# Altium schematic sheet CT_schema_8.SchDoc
size 254 x 194 mm
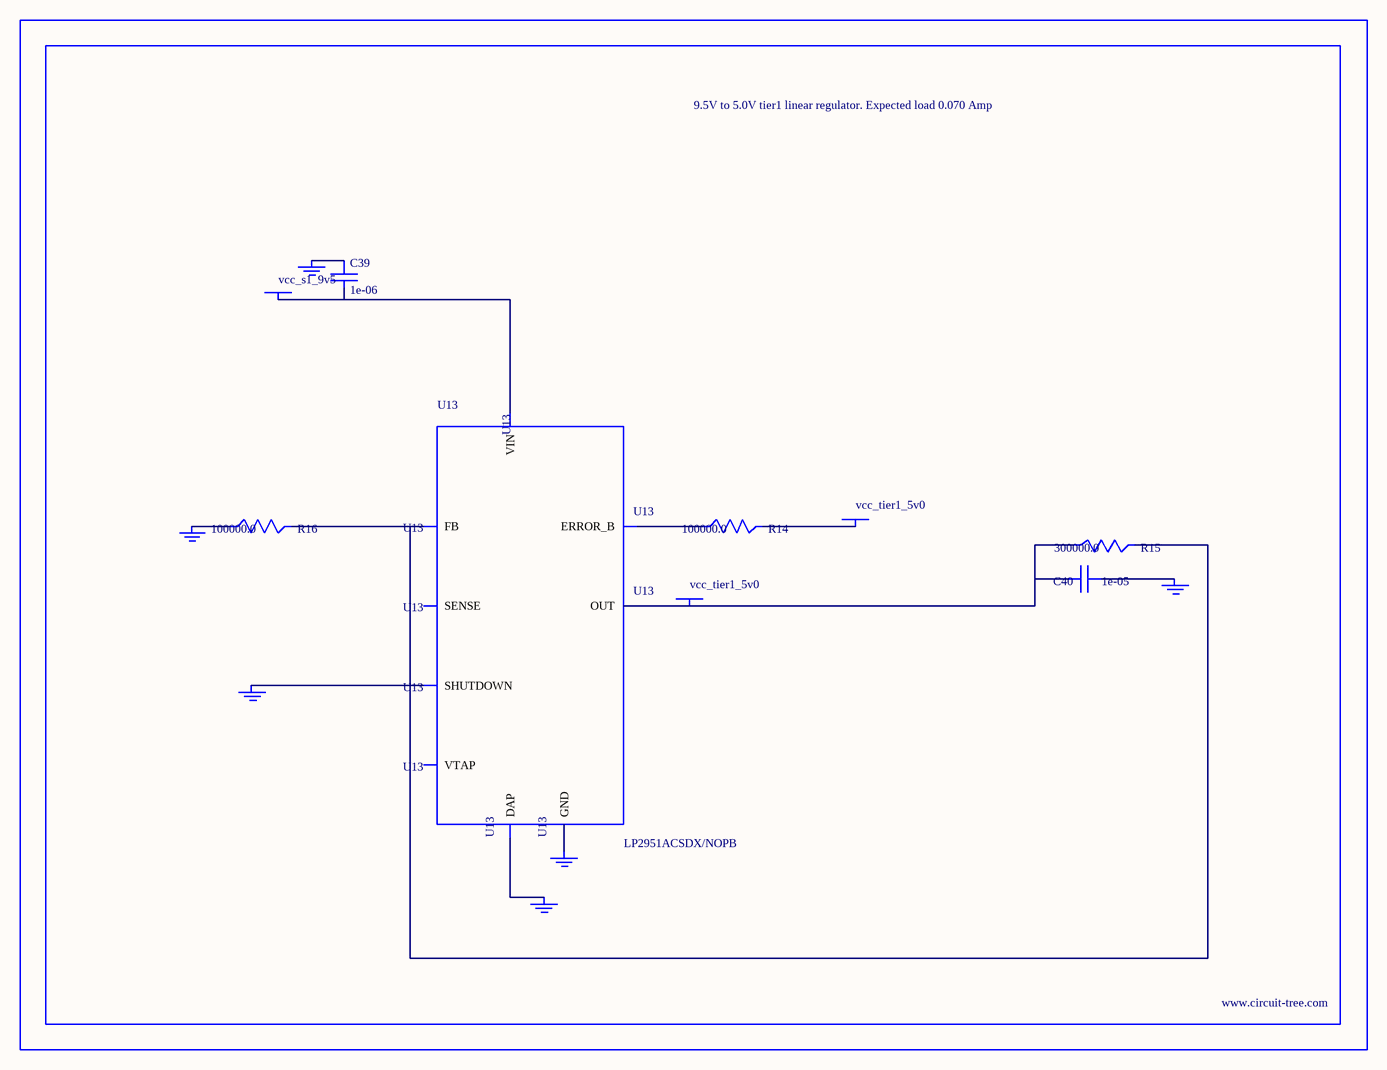
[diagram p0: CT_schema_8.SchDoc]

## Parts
BORDER7  (no value)
C39  1e-06  [C0603]
C40  1e-05  [C1210]
GND_INSTANCE_7_0  (no value)
GND_INSTANCE_7_1  (no value)
GND_INSTANCE_7_2  (no value)
GND_INSTANCE_7_3  (no value)
GND_INSTANCE_7_4  (no value)
GND_INSTANCE_7_5  (no value)
POWER_INSTANCE_7_0  vcc_tier1_5v0
POWER_INSTANCE_7_1  vcc_s1_9v5
POWER_INSTANCE_7_2  vcc_tier1_5v0
R14  100000.0  [R0603]
R15  300000.0  [R0603]
R16  100000.0  [R0603]
U13  LP2951ACSDX/NOPB  [WSON-8]

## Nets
NetC39_1: C39.1 GND_INSTANCE_7_3.0(GND)
NetC39_2: C39.2 POWER_INSTANCE_7_1.0(PWR) U13.8(VIN)
NetC40_1: C40.1 GND_INSTANCE_7_0.0(GND)
NetC40_2: C40.2 POWER_INSTANCE_7_2.0(PWR) R15.1 U13.1(OUT)
NetGND_INSTANCE_7_1_0: GND_INSTANCE_7_1.0(GND) U13.3(SHUTDOWN)
NetGND_INSTANCE_7_2_0: GND_INSTANCE_7_2.0(GND) R16.1
NetGND_INSTANCE_7_4_0: GND_INSTANCE_7_4.0(GND) U13.PAD(DAP)
NetGND_INSTANCE_7_5_0: GND_INSTANCE_7_5.0(GND) U13.4(GND)
NetPOWER_INSTANCE_7_0_0: POWER_INSTANCE_7_0.0(PWR) R14.2
NetR14_1: R14.1 U13.5(ERROR_B)
NetR15_2: R15.2 R16.2 U13.7(FB)

Not connected (* = marked no-connect by the designer): U13 2(SENSE) 6(VTAP)

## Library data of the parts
BORDER7 = BORDER_PAGE7
C39 = C0603C105K3RACTU
C40 = GRM32DR61E106MA12L
GND_INSTANCE_7_0-GND_INSTANCE_7_5 = GND
POWER_INSTANCE_7_0-POWER_INSTANCE_7_2 = PWR
R14 R16 = RC0603JR-07100KL
R15 = RC0603JR-07300KL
